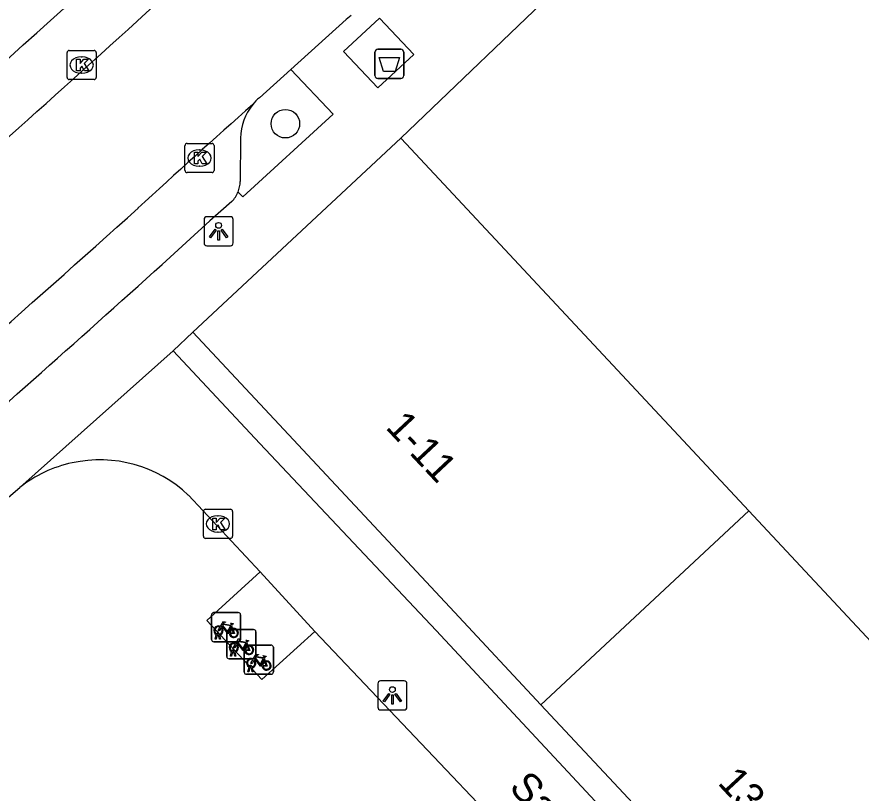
# Model space of a CAD drawing. Extents: x 162347 to 162868, y 381221 to 381813.
# Drawn here: x 162617.14 to 162646.11, y 381573.33 to 381599.97 of the extents above; entities that cross this region are included whole.
import ezdxf

# ---------------------------------------------------------------- set-up
doc = ezdxf.new("R2010")
doc.units = 0
for name, color, linetype in [('IMGEO_Afval_apart_plaats', 7, 'Continuous'), ('IMGEO_Boom', 7, 'Continuous'), ('IMGEO_Fietsenrek', 7, 'Continuous'), ('IMGEO_Kolk', 7, 'Continuous'), ('IMGEO_Lichtpunt', 7, 'Continuous'), ('IMGEO_Openbare_ruimte_label', 7, 'Continuous'), ('IMGEO_Pand', 7, 'Continuous'), ('IMGEO_Pand_nummerreeks', 7, 'Continuous'), ('IMGEO_Parkeervlak_open', 7, 'Continuous'), ('IMGEO_Rijbaan_lokaal_open', 7, 'Continuous'), ('IMGEO_Voetpad_gesloten', 7, 'Continuous'), ('IMGEO_Voetpad_open', 7, 'Continuous')]:
    doc.layers.add(name, color=color, linetype=linetype)

msp = doc.modelspace()

# ---------------------------------------------------------------- linework, layer by layer
at = {"layer": 'IMGEO_Afval_apart_plaats'}
for p, q in [((162629.424, 381597.955), (162629.424, 381598.755)), ((162629.424, 381598.755), (162629.424, 381597.955)), ((162629.524, 381598.855), (162630.314, 381598.855)), ((162630.314, 381598.855), (162629.524, 381598.855)), ((162630.414, 381598.755), (162630.414, 381597.955)), ((162630.414, 381597.955), (162630.414, 381598.755)), ((162630.314, 381597.855), (162629.524, 381597.855)), ((162629.524, 381597.855), (162630.314, 381597.855))]:
    msp.add_line(p, q, dxfattribs=at)
msp.add_lwpolyline([(162629.567, 381598.569), (162630.271, 381598.569), (162630.122, 381598.099), (162629.716, 381598.099), (162629.567, 381598.569)], dxfattribs=at)
for centre, start, end in [((162629.524, 381598.755), 90, 180), ((162629.524, 381598.755), 90, 180), ((162630.314, 381598.755), 0, 90), ((162630.314, 381598.755), 360, 90), ((162629.524, 381597.955), 180, 270), ((162629.524, 381597.955), 180, 270), ((162630.314, 381597.955), 270, 0), ((162630.314, 381597.955), 270, 0)]:
    msp.add_arc(centre, 0.1, start, end, dxfattribs=at)
at = {"layer": 'IMGEO_Boom'}
msp.add_circle((162626.353, 381596.301), 0.489, dxfattribs=at)
at = {"layer": 'IMGEO_Fietsenrek'}
for p, q in [((162623.89, 381579.523), (162624.731, 381579.523)), ((162624.731, 381579.523), (162623.89, 381579.523)), ((162623.815, 381578.598), (162623.815, 381579.439)), ((162623.815, 381579.439), (162623.815, 381578.598)), ((162624.815, 381579.448), (162624.815, 381578.607)), ((162624.815, 381578.607), (162624.815, 381579.448)), ((162624.416, 381578.939), (162625.257, 381578.939)), ((162625.257, 381578.939), (162624.416, 381578.939)), ((162624.502, 381579.072), (162624.538, 381578.977)), ((162623.942, 381578.607), (162623.981, 381578.767)), ((162624.011, 381578.755), (162623.976, 381578.607)), ((162624.053, 381578.779), (162624.052, 381578.783)), ((162624.094, 381578.607), (162624.06, 381578.749)), ((162624.084, 381578.79), (162624.085, 381578.783)), ((162624.092, 381578.753), (162624.127, 381578.607)), ((162624.341, 381578.014), (162624.341, 381578.855)), ((162624.341, 381578.855), (162624.341, 381578.014)), ((162625.341, 381578.864), (162625.341, 381578.023)), ((162625.341, 381578.023), (162625.341, 381578.864)), ((162624.74, 381578.523), (162623.899, 381578.523)), ((162623.899, 381578.523), (162624.74, 381578.523)), ((162623.976, 381578.607), (162623.942, 381578.607)), ((162624.127, 381578.607), (162624.094, 381578.607)), ((162625.014, 381578.406), (162625.855, 381578.406)), ((162625.855, 381578.406), (162625.014, 381578.406)), ((162625.028, 381578.488), (162625.064, 381578.393)), ((162625.939, 381578.331), (162625.939, 381577.49)), ((162625.939, 381577.49), (162625.939, 381578.331)), ((162624.468, 381578.023), (162624.507, 381578.183)), ((162624.537, 381578.171), (162624.502, 381578.023)), ((162624.579, 381578.195), (162624.578, 381578.199)), ((162624.62, 381578.023), (162624.586, 381578.165)), ((162624.61, 381578.206), (162624.611, 381578.199)), ((162624.618, 381578.169), (162624.653, 381578.023)), ((162624.939, 381577.481), (162624.939, 381578.322)), ((162624.939, 381578.322), (162624.939, 381577.481)), ((162625.266, 381577.939), (162624.425, 381577.939)), ((162624.425, 381577.939), (162625.266, 381577.939)), ((162624.502, 381578.023), (162624.468, 381578.023)), ((162624.653, 381578.023), (162624.62, 381578.023)), ((162625.626, 381577.955), (162625.662, 381577.86)), ((162625.066, 381577.49), (162625.105, 381577.65)), ((162625.1, 381577.49), (162625.066, 381577.49)), ((162625.135, 381577.638), (162625.1, 381577.49)), ((162625.177, 381577.662), (162625.176, 381577.666)), ((162625.218, 381577.49), (162625.184, 381577.632)), ((162625.208, 381577.673), (162625.209, 381577.666)), ((162625.216, 381577.636), (162625.251, 381577.49)), ((162625.251, 381577.49), (162625.218, 381577.49)), ((162625.864, 381577.406), (162625.023, 381577.406)), ((162625.023, 381577.406), (162625.864, 381577.406))]:
    msp.add_line(p, q, dxfattribs=at)
for points in [[(162624.128, 381579.049), (162624.223, 381579.213), (162624.309, 381579.199), (162624.311, 381579.19), (162624.255, 381579.179), (162624.228, 381579.134), (162624.484, 381579.093)], [(162624.149, 381578.997), (162624.097, 381578.907), (162624.057, 381578.882), (162624.058, 381578.929), (162624.113, 381579.023)], [(162624.424, 381578.805), (162624.374, 381578.805), (162624.183, 381579.056), (162624.164, 381579.024)], [(162624.471, 381579.068), (162624.214, 381579.109), (162624.197, 381579.08), (162624.364, 381578.86), (162624.471, 381579.068)], [(162624.519, 381578.97), (162624.489, 381579.047), (162624.38, 381578.829), (162624.423, 381578.829)], [(162624.453, 381578.829), (162624.573, 381578.828), (162624.529, 381578.942)], [(162624.549, 381578.949), (162624.604, 381578.804), (162624.454, 381578.804)], [(162624.484, 381579.093), (162624.509, 381579.142), (162624.503, 381579.146), (162624.48, 381579.15), (162624.468, 381579.157), (162624.467, 381579.16), (162624.469, 381579.165), (162624.564, 381579.15), (162624.566, 381579.14), (162624.556, 381579.127), (162624.544, 381579.121), (162624.53, 381579.127), (162624.502, 381579.072)], [(162624.654, 381578.465), (162624.749, 381578.629), (162624.835, 381578.615), (162624.837, 381578.606), (162624.781, 381578.595), (162624.754, 381578.55), (162625.01, 381578.509)], [(162624.675, 381578.413), (162624.623, 381578.323), (162624.583, 381578.298), (162624.584, 381578.345), (162624.639, 381578.439)], [(162624.95, 381578.221), (162624.9, 381578.221), (162624.709, 381578.472), (162624.69, 381578.44)], [(162624.997, 381578.484), (162624.74, 381578.525), (162624.723, 381578.496), (162624.89, 381578.276), (162624.997, 381578.484)], [(162625.045, 381578.386), (162625.015, 381578.463), (162624.906, 381578.245), (162624.949, 381578.245)], [(162624.979, 381578.245), (162625.099, 381578.244), (162625.055, 381578.358)], [(162625.075, 381578.365), (162625.13, 381578.22), (162624.98, 381578.22)], [(162625.01, 381578.509), (162625.035, 381578.558), (162625.029, 381578.562), (162625.006, 381578.566), (162624.994, 381578.573), (162624.993, 381578.576), (162624.995, 381578.581), (162625.09, 381578.566), (162625.092, 381578.556), (162625.082, 381578.543), (162625.07, 381578.537), (162625.056, 381578.543), (162625.028, 381578.488)], [(162625.252, 381577.932), (162625.347, 381578.096), (162625.433, 381578.082), (162625.435, 381578.073), (162625.379, 381578.062), (162625.352, 381578.017), (162625.608, 381577.976)], [(162625.608, 381577.976), (162625.633, 381578.025), (162625.627, 381578.029), (162625.604, 381578.033), (162625.592, 381578.04), (162625.591, 381578.043), (162625.593, 381578.048), (162625.688, 381578.033), (162625.69, 381578.023), (162625.68, 381578.01), (162625.668, 381578.004), (162625.654, 381578.01), (162625.626, 381577.955)], [(162625.273, 381577.88), (162625.221, 381577.79), (162625.181, 381577.765), (162625.182, 381577.812), (162625.237, 381577.906)], [(162625.548, 381577.688), (162625.498, 381577.688), (162625.307, 381577.939), (162625.288, 381577.907)], [(162625.595, 381577.951), (162625.338, 381577.992), (162625.321, 381577.963), (162625.488, 381577.743), (162625.595, 381577.951)], [(162625.643, 381577.853), (162625.613, 381577.93), (162625.504, 381577.712), (162625.547, 381577.712)], [(162625.577, 381577.712), (162625.697, 381577.711), (162625.653, 381577.825)], [(162625.673, 381577.832), (162625.728, 381577.687), (162625.578, 381577.687)]]:
    msp.add_lwpolyline(points, dxfattribs=at)
for centre, radius, start, end in [((162623.893, 381579.445), 0.0779, 92.4484, 184.2845), ((162623.893, 381579.445), 0.0779, 92.4484, 184.2845), ((162624.737, 381579.445), 0.0779, 2.4484, 94.2845), ((162624.737, 381579.445), 0.0779, 2.4484, 94.2845), ((162624.055, 381578.908), 0.159, 62.6766, 242.1369), ((162624.055, 381578.908), 0.129, 63.3192, 238.903), ((162624.055, 381578.908), 0.129, 283.6043, 43.4302), ((162624.055, 381578.908), 0.159, 283.5766, 46.6042), ((162624.419, 381578.861), 0.0779, 92.4484, 184.2845), ((162624.419, 381578.861), 0.0779, 92.4484, 184.2845), ((162624.582, 381578.824), 0.159, 113.3408, 178.3217), ((162624.582, 381578.824), 0.159, 187.0065, 105.7708), ((162624.582, 381578.824), 0.129, 113.923, 177.9556), ((162624.582, 381578.824), 0.129, 188.6715, 104.5883), ((162625.263, 381578.861), 0.0779, 2.4484, 94.2845), ((162625.263, 381578.861), 0.0779, 2.4484, 94.2845), ((162624.035, 381578.779), 0.0499, 12.8025, 158.6934), ((162624.055, 381578.908), 0.159, 253.9967, 271.7867), ((162624.035, 381578.779), 0.0174, 12.8025, 163.4502), ((162624.055, 381578.908), 0.129, 253.415, 269.0204), ((162623.893, 381578.601), 0.0779, 182.4484, 274.2845), ((162623.893, 381578.601), 0.0779, 182.4484, 274.2845), ((162624.581, 381578.324), 0.159, 62.6766, 242.1369), ((162624.581, 381578.324), 0.129, 63.3192, 238.903), ((162624.581, 381578.324), 0.129, 283.6043, 43.4302), ((162624.581, 381578.324), 0.159, 283.5766, 46.6042), ((162624.737, 381578.601), 0.0779, 272.4484, 4.2845), ((162624.737, 381578.601), 0.0779, 272.4484, 4.2845), ((162625.017, 381578.328), 0.0779, 92.4484, 184.2845), ((162625.017, 381578.328), 0.0779, 92.4484, 184.2845), ((162625.108, 381578.24), 0.159, 113.3408, 178.3217), ((162625.108, 381578.24), 0.159, 187.0065, 105.7708), ((162625.108, 381578.24), 0.129, 113.923, 177.9556), ((162625.108, 381578.24), 0.129, 188.6715, 104.5883), ((162625.861, 381578.328), 0.0779, 2.4484, 94.2845), ((162625.861, 381578.328), 0.0779, 2.4484, 94.2845), ((162624.561, 381578.195), 0.0499, 12.8025, 158.6934), ((162624.581, 381578.324), 0.159, 253.9967, 271.7867), ((162624.561, 381578.195), 0.0174, 12.8025, 163.4502), ((162624.581, 381578.324), 0.129, 253.415, 269.0204), ((162624.419, 381578.017), 0.0779, 182.4484, 274.2845), ((162624.419, 381578.017), 0.0779, 182.4484, 274.2845), ((162625.179, 381577.791), 0.159, 62.6766, 242.1369), ((162625.179, 381577.791), 0.129, 63.3192, 238.903), ((162625.179, 381577.791), 0.129, 283.6043, 43.4302), ((162625.179, 381577.791), 0.159, 283.5766, 46.6042), ((162625.263, 381578.017), 0.0779, 272.4484, 4.2845), ((162625.263, 381578.017), 0.0779, 272.4484, 4.2845), ((162625.706, 381577.707), 0.159, 113.3408, 178.3217), ((162625.706, 381577.707), 0.159, 187.0065, 105.7708), ((162625.706, 381577.707), 0.129, 113.923, 177.9556), ((162625.706, 381577.707), 0.129, 188.6715, 104.5883), ((162625.017, 381577.484), 0.0779, 182.4484, 274.2845), ((162625.017, 381577.484), 0.0779, 182.4484, 274.2845), ((162625.159, 381577.662), 0.0499, 12.8025, 158.6934), ((162625.179, 381577.791), 0.159, 253.9967, 271.7867), ((162625.159, 381577.662), 0.0174, 12.8025, 163.4502), ((162625.179, 381577.791), 0.129, 253.415, 269.0204), ((162625.861, 381577.484), 0.0779, 272.4484, 4.2845), ((162625.861, 381577.484), 0.0779, 272.4484, 4.2845)]:
    msp.add_arc(centre, radius, start, end, dxfattribs=at)
at = {"layer": 'IMGEO_Kolk'}
for p, q in [((162618.861, 381597.89), (162618.861, 381598.742)), ((162618.936, 381598.816), (162619.788, 381598.816)), ((162619.862, 381598.742), (162619.862, 381597.89)), ((162619.349, 381598.596), (162619.374, 381598.596)), ((162619.372, 381598.036), (162619.347, 381598.036)), ((162619.788, 381597.816), (162618.936, 381597.816)), ((162622.907, 381594.698), (162622.907, 381595.55)), ((162622.982, 381595.624), (162623.834, 381595.624)), ((162623.908, 381595.55), (162623.908, 381594.698)), ((162623.395, 381595.404), (162623.42, 381595.404)), ((162623.418, 381594.844), (162623.393, 381594.844)), ((162623.834, 381594.624), (162622.982, 381594.624)), ((162623.537, 381582.141), (162623.537, 381582.993)), ((162623.612, 381583.067), (162624.464, 381583.067)), ((162624.538, 381582.993), (162624.538, 381582.141)), ((162624.025, 381582.847), (162624.05, 381582.847)), ((162624.048, 381582.287), (162624.023, 381582.287)), ((162624.464, 381582.067), (162623.612, 381582.067))]:
    msp.add_line(p, q, dxfattribs=at)
for points in [[(162618.861, 381597.89), (162618.861, 381598.742)], [(162618.936, 381598.816), (162619.788, 381598.816)], [(162619.862, 381598.742), (162619.862, 381597.89)], [(162619.182, 381598.516), (162619.305, 381598.516), (162619.305, 381598.365), (162619.435, 381598.516), (162619.599, 381598.516), (162619.453, 381598.365), (162619.606, 381598.116), (162619.454, 381598.116), (162619.369, 381598.28), (162619.305, 381598.213), (162619.305, 381598.116), (162619.182, 381598.116), (162619.182, 381598.516)], [(162619.788, 381597.816), (162618.936, 381597.816)], [(162622.907, 381594.698), (162622.907, 381595.55)], [(162622.982, 381595.624), (162623.834, 381595.624)], [(162623.908, 381595.55), (162623.908, 381594.698)], [(162623.228, 381595.324), (162623.351, 381595.324), (162623.351, 381595.173), (162623.481, 381595.324), (162623.645, 381595.324), (162623.499, 381595.173), (162623.652, 381594.924), (162623.5, 381594.924), (162623.415, 381595.088), (162623.351, 381595.021), (162623.351, 381594.924), (162623.228, 381594.924), (162623.228, 381595.324)], [(162623.834, 381594.624), (162622.982, 381594.624)], [(162623.537, 381582.141), (162623.537, 381582.993)], [(162623.612, 381583.067), (162624.464, 381583.067)], [(162624.538, 381582.993), (162624.538, 381582.141)], [(162623.858, 381582.767), (162623.981, 381582.767), (162623.981, 381582.616), (162624.111, 381582.767), (162624.275, 381582.767), (162624.129, 381582.616), (162624.282, 381582.367), (162624.13, 381582.367), (162624.045, 381582.531), (162623.981, 381582.464), (162623.981, 381582.367), (162623.858, 381582.367), (162623.858, 381582.767)], [(162624.464, 381582.067), (162623.612, 381582.067)]]:
    msp.add_lwpolyline(points, dxfattribs=at)
for centre, start, end in [((162618.938, 381598.74), 91.552, 178.448), ((162618.938, 381598.74), 91.552, 178.448), ((162619.786, 381598.74), 1.552, 88.448), ((162619.786, 381598.74), 1.552, 88.448), ((162618.938, 381597.892), 181.552, 268.448), ((162618.938, 381597.892), 181.552, 268.448), ((162619.786, 381597.892), 271.552, 358.448), ((162619.786, 381597.892), 271.552, 358.448), ((162622.984, 381595.548), 91.552, 178.448), ((162622.984, 381595.548), 91.552, 178.448), ((162623.832, 381595.548), 1.552, 88.448), ((162623.832, 381595.548), 1.552, 88.448), ((162622.984, 381594.7), 181.552, 268.448), ((162622.984, 381594.7), 181.552, 268.448), ((162623.832, 381594.7), 271.552, 358.448), ((162623.832, 381594.7), 271.552, 358.448), ((162623.614, 381582.991), 91.552, 178.448), ((162623.614, 381582.991), 91.552, 178.448), ((162624.462, 381582.991), 1.552, 88.448), ((162624.462, 381582.991), 1.552, 88.448), ((162623.614, 381582.143), 181.552, 268.448), ((162623.614, 381582.143), 181.552, 268.448), ((162624.462, 381582.143), 271.552, 358.448), ((162624.462, 381582.143), 271.552, 358.448)]:
    msp.add_arc(centre, 0.0765, start, end, dxfattribs=at)
for centre, major_axis, ratio, start_param, end_param in [((162619.348, 381598.316), (-0.387, 0.002), 0.722429, 4.712389, 7.853982), ((162619.373, 381598.316), (-0.39, 0.002), 0.717154, 1.570796, 4.712389), ((162623.394, 381595.124), (-0.387, 0.002), 0.722429, 4.712389, 7.853982), ((162623.419, 381595.124), (-0.39, 0.002), 0.717154, 1.570796, 4.712389), ((162624.024, 381582.567), (-0.387, 0.002), 0.722429, 4.712389, 7.853982), ((162624.049, 381582.567), (-0.39, 0.002), 0.717154, 1.570796, 4.712389)]:
    msp.add_ellipse(centre, major_axis=major_axis, ratio=ratio, start_param=start_param, end_param=end_param, dxfattribs=at)
at = {"layer": 'IMGEO_Lichtpunt'}
for p, q in [((162624.465, 381593.11), (162623.657, 381593.11)), ((162624.465, 381593.11), (162623.657, 381593.11)), ((162623.563, 381593.015), (162623.563, 381592.208)), ((162623.563, 381593.015), (162623.563, 381592.208)), ((162624.559, 381592.208), (162624.559, 381593.015)), ((162624.559, 381592.208), (162624.559, 381593.015)), ((162623.657, 381592.114), (162624.465, 381592.114)), ((162623.657, 381592.114), (162624.465, 381592.114)), ((162630.427, 381577.178), (162629.619, 381577.178)), ((162630.427, 381577.178), (162629.619, 381577.178)), ((162629.525, 381577.083), (162629.525, 381576.276)), ((162629.525, 381577.083), (162629.525, 381576.276)), ((162630.521, 381576.276), (162630.521, 381577.083)), ((162630.521, 381576.276), (162630.521, 381577.083)), ((162629.619, 381576.182), (162630.427, 381576.182)), ((162629.619, 381576.182), (162630.427, 381576.182))]:
    msp.add_line(p, q, dxfattribs=at)
for points in [[(162623.937, 381592.679), (162623.976, 381592.651), (162623.788, 381592.389), (162623.75, 381592.416), (162623.937, 381592.679)], [(162624.039, 381592.631), (162624.086, 381592.631), (162624.086, 381592.309), (162624.039, 381592.309), (162624.039, 381592.631)], [(162624.149, 381592.651), (162624.187, 381592.678), (162624.374, 381592.416), (162624.335, 381592.388), (162624.149, 381592.651)], [(162629.899, 381576.747), (162629.938, 381576.719), (162629.75, 381576.457), (162629.712, 381576.484), (162629.899, 381576.747)], [(162630.001, 381576.699), (162630.048, 381576.699), (162630.048, 381576.377), (162630.001, 381576.377), (162630.001, 381576.699)], [(162630.111, 381576.719), (162630.149, 381576.746), (162630.336, 381576.484), (162630.297, 381576.456), (162630.111, 381576.719)]]:
    msp.add_lwpolyline(points, dxfattribs=at)
for centre in [(162624.062, 381592.813), (162630.024, 381576.881)]:
    msp.add_circle(centre, 0.0994, dxfattribs=at)
for centre, start, end in [((162623.657, 381593.015), 90, 180), ((162623.657, 381593.015), 90, 180), ((162624.465, 381593.015), 0, 90), ((162624.465, 381593.015), 0, 90), ((162623.657, 381592.208), 180, 270), ((162623.657, 381592.208), 180, 270), ((162624.465, 381592.208), 270, 0), ((162624.465, 381592.208), 270, 360), ((162629.619, 381577.083), 90, 180), ((162629.619, 381577.083), 90, 180), ((162630.427, 381577.083), 0, 90), ((162630.427, 381577.083), 0, 90), ((162629.619, 381576.276), 180, 270), ((162629.619, 381576.276), 180, 270), ((162630.427, 381576.276), 270, 0), ((162630.427, 381576.276), 270, 360)]:
    msp.add_arc(centre, 0.0946, start, end, dxfattribs=at)
at = {"layer": 'IMGEO_Pand'}
for points in [[(162623.179, 381589.147), (162630.312, 381595.808)], [(162642.256, 381583.018), (162630.497, 381595.61), (162630.312, 381595.808)], [(162623.179, 381589.147), (162626.135, 381585.982), (162632.154, 381579.537), (162635.123, 381576.357)], [(162635.123, 381576.357), (162642.256, 381583.018)], [(162642.256, 381583.018), (162654.2, 381570.228)], [(162647.067, 381563.566), (162644.391, 381566.431), (162637.954, 381573.325), (162635.123, 381576.357)]]:
    msp.add_lwpolyline(points, dxfattribs=at)
at = {"layer": 'IMGEO_Parkeervlak_open'}
msp.add_lwpolyline([(162624.81, 381595.811), (162624.806, 381594.321)], dxfattribs=at)
for centre, radius, start, end in [((162626.688, 381595.772), 1.879, 140.7714, 178.8066), ((162623.713, 381594.369), 1.094, 337.9432, 357.501)]:
    msp.add_arc(centre, radius, start, end, dxfattribs=at)
at = {"layer": 'IMGEO_Rijbaan_lokaal_open'}
for points in [[(162628.605, 381600.016), (162628.438, 381599.881), (162626.535, 381598.164)], [(162626.535, 381598.164), (162625.462, 381597.195)]]:
    msp.add_lwpolyline(points, dxfattribs=at)
for centre, radius, start, end in [((161942.339, 382348.939), 1011, 311.016557, 312.544247), ((162626.584, 381595.873), 1.734, 130.3126, 141.1691), ((162784.883, 381416.3), 241.094, 131.4673, 132.7286), ((162205.379, 382055.51), 621.715, 310.553643, 311.98853)]:
    msp.add_arc(centre, radius, start, end, dxfattribs=at)
at = {"layer": 'IMGEO_Voetpad_gesloten'}
msp.add_lwpolyline([(162629.577, 381599.921), (162630.755, 381598.683), (162629.526, 381597.537), (162628.35, 381598.785), (162629.577, 381599.921)], dxfattribs=at)
at = {"layer": 'IMGEO_Voetpad_open'}
for points in [[(162630.312, 381595.808), (162647.237, 381612.021)], [(162626.535, 381598.164), (162627.989, 381596.627), (162624.893, 381593.79), (162624.727, 381593.958)], [(162624.514, 381593.629), (162623.764, 381592.972)], [(162622.507, 381588.51), (162623.179, 381589.147)], [(162617.236, 381583.812), (162622.507, 381588.51)], [(162658.64, 381550.091), (162655.573, 381553.411), (162649.537, 381559.582), (162643.742, 381565.799), (162637.295, 381572.722), (162631.525, 381578.914), (162625.475, 381585.332), (162622.507, 381588.51)], [(162599.604, 381568.769), (162617.236, 381583.812)], [(162623.022, 381583.552), (162625.486, 381580.925)], [(162625.486, 381580.925), (162623.651, 381579.251), (162625.549, 381577.221), (162627.368, 381578.875)], [(162625.486, 381580.925), (162627.368, 381578.875)], [(162627.368, 381578.875), (162637.445, 381568.255)]]:
    msp.add_lwpolyline(points, dxfattribs=at)
for centre, radius, start, end in [((162012.532, 382272.566), 905.263, 311.328974, 312.594769), ((162623.741, 381594.363), 1.066, 316.4832, 337.6774), ((162286.159, 381962.013), 500.168, 311.09424, 312.45287), ((162619.984, 381580.358), 4.408, 46.4362, 102.4074), ((162619.944, 381580.412), 4.347, 102.0468, 128.5361)]:
    msp.add_arc(centre, radius, start, end, dxfattribs=at)

# ---------------------------------------------------------------- texts
at = {"layer": 'IMGEO_Openbare_ruimte_label'}
msp.add_text('Salviapad', height=1, rotation=313.2177, dxfattribs=at).set_placement((162633.991, 381573.492))
at = {"layer": 'IMGEO_Pand_nummerreeks'}
for s, rotation, p in [('1-11', 313.1598, (162629.76, 381585.862)), ('13-23', 312.8195, (162641.155, 381573.661))]:
    msp.add_text(s, height=1, rotation=rotation, dxfattribs=at).set_placement(p)

doc.saveas('drawing.dxf')
